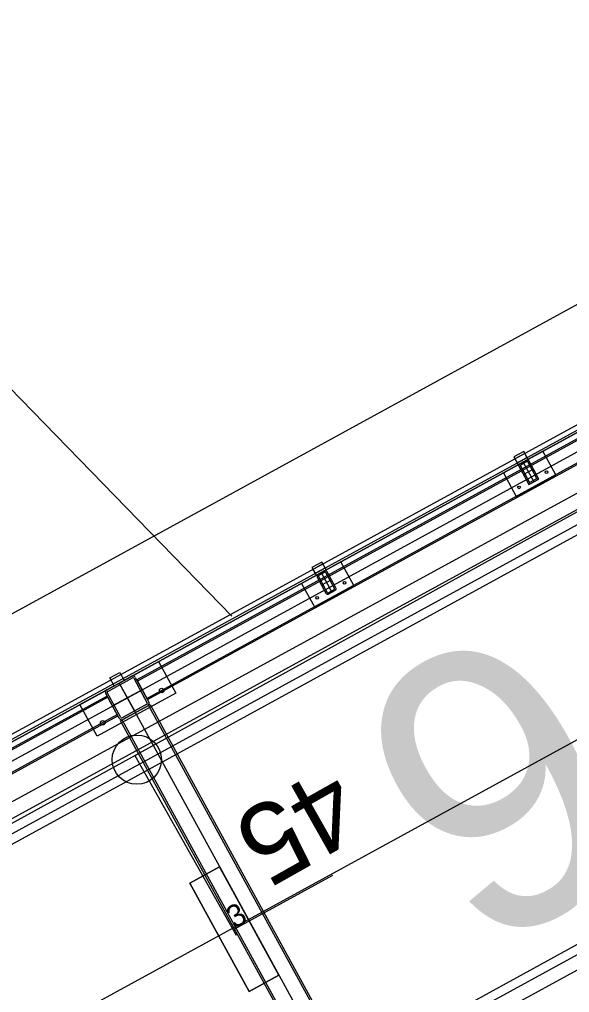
# Model space of a CAD drawing. Extents: x -783978 to -783565, y -1064821 to -1064596.
# Drawn here: x -783781.623 to -783779.173, y -1064690.963 to -1064686.63 of the extents above; entities that cross this region are included whole.
import ezdxf

# ---------------------------------------------------------------- set-up
doc = ezdxf.new("R2010")
doc.units = 0
for name, color, linetype in [('_PS_SO_číslo', 7, 'Continuous'), ('Default', 7, 'Continuous'), ('SO 01_20_01', 7, 'Continuous'), ('SO 01_50_01', 7, 'Continuous'), ('SO 01_74_01', 7, 'Continuous'), ('SO 01_77_01', 7, 'Continuous'), ('SO 01_86_04', 7, 'Continuous')]:
    doc.layers.add(name, color=color, linetype=linetype)

# ---------------------------------------------------------------- blocks, each defined once
blk = doc.blocks.new('POINT_DISPLAY')
at = {"layer": 'Default'}
blk.add_line((0, 0), (0, 0), dxfattribs=at)

msp = doc.modelspace()

# ---------------------------------------------------------------- linework, layer by layer
at = {"layer": '_PS_SO_číslo'}
msp.add_line((-783780.6769, -1064689.2872), (-783798.2896, -1064671.1829), dxfattribs=at)
at = {"layer": 'SO 01_20_01'}
for p, q in [((-783735.0054, -1064663.7532), (-783787.4671, -1064692.4555)), ((-783735.2041, -1064664.4318), (-783786.7885, -1064692.6541)), ((-783786.6445, -1064692.9173), (-783735.3233, -1064664.839)), ((-783738.0171, -1064666.3812), (-783786.4402, -1064692.874)), ((-783786.421, -1064692.9091), (-783737.9979, -1064666.4163)), ((-783737.8741, -1064667.2605), (-783785.3352, -1064693.2269)), ((-783785.6531, -1064694.3127), (-783737.23, -1064667.82)), ((-783737.0912, -1064667.858), (-783785.7805, -1064694.4964)), ((-783737.2108, -1064667.855), (-783785.6339, -1064694.3478))]:
    msp.add_line(p, q, dxfattribs=at)
at = {"layer": 'SO 01_50_01'}
for p, q in [((-783786.7885, -1064692.6541), (-783725.4827, -1064659.1131)), ((-783782.4021, -1064690.2543), (-783778.0156, -1064687.8544)), ((-783782.402, -1064690.2544), (-783778.0156, -1064687.8545)), ((-783782.402, -1064690.2544), (-783778.0156, -1064687.8545))]:
    msp.add_line(p, q, dxfattribs=at)
at = {"layer": 'SO 01_74_01'}
for p, q in [((-783735.2185, -1064664.4055), (-783786.6099, -1064692.5222)), ((-783786.6003, -1064692.5398), (-783735.2089, -1064664.423)), ((-783778.5344, -1064688.1667), (-783781.1005, -1064689.5707)), ((-783778.5314, -1064688.1723), (-783781.0974, -1064689.5762)), ((-783781.0555, -1064689.6529), (-783778.4894, -1064688.2489)), ((-783781.0525, -1064689.6584), (-783778.4864, -1064688.2545)), ((-783779.3771, -1064688.5537), (-783779.421, -1064688.5777)), ((-783779.421, -1064688.5777), (-783779.4018, -1064688.6128)), ((-783779.3723, -1064688.5625), (-783779.4162, -1064688.5865)), ((-783779.4162, -1064688.5865), (-783779.4066, -1064688.604)), ((-783779.4066, -1064688.604), (-783779.3627, -1064688.58)), ((-783779.4018, -1064688.6128), (-783779.3579, -1064688.5888)), ((-783779.3579, -1064688.5888), (-783779.3771, -1064688.5537)), ((-783779.3627, -1064688.58), (-783779.3723, -1064688.5625)), ((-783780.2763, -1064689.0457), (-783780.3202, -1064689.0697)), ((-783780.3202, -1064689.0697), (-783780.301, -1064689.1048)), ((-783780.2715, -1064689.0544), (-783780.3154, -1064689.0784)), ((-783780.2571, -1064689.0808), (-783780.2763, -1064689.0457)), ((-783780.2619, -1064689.072), (-783780.2715, -1064689.0544)), ((-783780.3154, -1064689.0784), (-783780.3058, -1064689.096)), ((-783780.3058, -1064689.096), (-783780.2619, -1064689.072)), ((-783780.301, -1064689.1048), (-783780.2571, -1064689.0808)), ((-783781.2194, -1064689.5616), (-783781.1755, -1064689.5376)), ((-783781.1755, -1064689.5376), (-783781.1563, -1064689.5727)), ((-783781.2002, -1064689.5967), (-783781.2194, -1064689.5616)), ((-783781.1563, -1064689.5727), (-783781.2002, -1064689.5967)), ((-783781.1005, -1064689.5707), (-783781.0525, -1064689.6584)), ((-783781.0974, -1064689.5762), (-783781.0555, -1064689.6529)), ((-783781.232, -1064689.6427), (-783783.7981, -1064691.0466)), ((-783781.229, -1064689.6482), (-783783.7951, -1064691.0521)), ((-783781.1841, -1064689.7304), (-783781.232, -1064689.6427)), ((-783781.1871, -1064689.7249), (-783781.229, -1064689.6482)), ((-783781.1721, -1064689.7523), (-783781.0405, -1064689.6803)), ((-783781.165, -1064689.7485), (-783781.0475, -1064689.6842)), ((-783781.0475, -1064689.6842), (-783780.0395, -1064691.5265)), ((-783781.0405, -1064689.6803), (-783780.0325, -1064691.5226)), ((-783783.7531, -1064691.1288), (-783781.1871, -1064689.7249)), ((-783783.7501, -1064691.1343), (-783781.1841, -1064689.7304)), ((-783780.1641, -1064691.5946), (-783781.1721, -1064689.7523)), ((-783780.1571, -1064691.5908), (-783781.165, -1064689.7485))]:
    msp.add_line(p, q, dxfattribs=at)
for points in [[(-783735.1681, -1064664.4976), (-783787.4762, -1064693.1159)], [(-783779.3662, -1064688.5933), (-783779.3935, -1064688.6082)], [(-783779.3972, -1064688.6211), (-783779.3583, -1064688.6922)], [(-783779.3917, -1064688.618), (-783779.3528, -1064688.6892)], [(-783779.3632, -1064688.5988), (-783779.3904, -1064688.6138)], [(-783779.3798, -1064688.6008), (-783779.3318, -1064688.6885)], [(-783779.3339, -1064688.6326), (-783779.3778, -1064688.6566)], [(-783779.32, -1064688.6712), (-783779.3589, -1064688.6001)], [(-783779.3144, -1064688.6682), (-783779.3534, -1064688.5971)], [(-783779.3485, -1064688.6904), (-783779.3212, -1064688.6755)], [(-783779.3455, -1064688.696), (-783779.3182, -1064688.681)], [(-783780.2964, -1064689.113), (-783780.2575, -1064689.1842)], [(-783780.2654, -1064689.0853), (-783780.2927, -1064689.1002)], [(-783780.2909, -1064689.11), (-783780.252, -1064689.1812)], [(-783780.2624, -1064689.0908), (-783780.2897, -1064689.1057)], [(-783780.279, -1064689.0928), (-783780.231, -1064689.1805)], [(-783780.2192, -1064689.1632), (-783780.2581, -1064689.0921)], [(-783780.2136, -1064689.1602), (-783780.2526, -1064689.089)], [(-783780.2331, -1064689.1246), (-783780.277, -1064689.1486)], [(-783780.2477, -1064689.1824), (-783780.2204, -1064689.1675)], [(-783780.2447, -1064689.1879), (-783780.2174, -1064689.173)], [(-783781.2335, -1064689.615), (-783781.123, -1064689.5545)], [(-783781.2297, -1064689.622), (-783781.1191, -1064689.5615)], [(-783781.1783, -1064689.5847), (-783780.0263, -1064691.6902)], [(-783781.1783, -1064689.5847), (-783781.1063, -1064689.7163)], [(-783781.1137, -1064689.5631), (-783781.0532, -1064689.6736)], [(-783781.1067, -1064689.5593), (-783781.0462, -1064689.6698)], [(-783781.1778, -1064689.7418), (-783781.2383, -1064689.6312)], [(-783781.1708, -1064689.7379), (-783781.2313, -1064689.6274)], [(-783781.0765, -1064689.6145), (-783781.2081, -1064689.6865)], [(-783781.0548, -1064689.6791), (-783781.1654, -1064689.7395)], [(-783781.051, -1064689.6861), (-783781.1615, -1064689.7466)]]:
    msp.add_lwpolyline(points, dxfattribs=at)
for points in [[(-783779.2921, -1064688.5528), (-783779.4675, -1064688.6488), (-783779.41, -1064688.7541), (-783779.2345, -1064688.6581)], [(-783779.3579, -1064688.5888), (-783779.4018, -1064688.6128), (-783779.3538, -1064688.7005), (-783779.3099, -1064688.6765)], [(-783780.1913, -1064689.0448), (-783780.3668, -1064689.1408), (-783780.3092, -1064689.246), (-783780.1337, -1064689.15)], [(-783780.926, -1064689.6291), (-783781.2769, -1064689.8211), (-783781.3537, -1064689.6807), (-783781.0028, -1064689.4887)]]:
    msp.add_lwpolyline(points, close=True, dxfattribs=at)
for centre, radius in [((-783779.2752, -1064688.6461), 0.006), ((-783779.398, -1064688.7133), 0.006), ((-783780.1744, -1064689.1381), 0.006), ((-783780.2972, -1064689.2053), 0.006), ((-783780.9891, -1064689.618), 0.01), ((-783781.2522, -1064689.762), 0.01)]:
    msp.add_circle(centre, radius, dxfattribs=at)
for centre, radius, start, end in [((-783779.3616, -1064688.6016), 0.00945, 28.6835, 118.6835), ((-783779.3889, -1064688.6165), 0.00945, 118.6835, 208.6835), ((-783779.3889, -1064688.6165), 0.00315, 118.6835, 208.6835), ((-783779.3616, -1064688.6016), 0.00315, 28.6835, 118.6835), ((-783779.3227, -1064688.6728), 0.00315, 298.6835, 28.6835), ((-783779.3227, -1064688.6728), 0.00945, 298.6835, 28.6835), ((-783779.35, -1064688.6877), 0.00945, 208.6835, 298.6835), ((-783779.35, -1064688.6877), 0.00315, 208.6835, 298.6835), ((-783780.2881, -1064689.1085), 0.00945, 118.6835, 208.6835), ((-783780.2881, -1064689.1085), 0.00315, 118.6835, 208.6835), ((-783780.2609, -1064689.0936), 0.00945, 28.6835, 118.6835), ((-783780.2609, -1064689.0936), 0.00315, 28.6835, 118.6835), ((-783780.2492, -1064689.1797), 0.00945, 208.6835, 298.6835), ((-783780.2492, -1064689.1797), 0.00315, 208.6835, 298.6835), ((-783780.2219, -1064689.1647), 0.00315, 298.6835, 28.6835), ((-783780.2219, -1064689.1647), 0.00945, 298.6835, 28.6835), ((-783781.1172, -1064689.565), 0.012, 28.6835, 118.6835), ((-783781.1172, -1064689.565), 0.004, 28.6835, 118.6835), ((-783781.2278, -1064689.6255), 0.012, 118.6835, 208.6835), ((-783781.2278, -1064689.6255), 0.004, 118.6835, 208.6835), ((-783781.0567, -1064689.6756), 0.004, 298.6835, 28.6835), ((-783781.0567, -1064689.6756), 0.012, 298.6835, 28.6835), ((-783781.1673, -1064689.736), 0.012, 208.6835, 298.6835), ((-783781.1673, -1064689.736), 0.004, 208.6835, 298.6835)]:
    msp.add_arc(centre, radius, start, end, dxfattribs=at)
at = {"layer": 'SO 01_86_04'}
for p, q in [((-783781.1089, -1064689.9078), (-783780.657, -1064690.7079)), ((-783780.7319, -1064690.4035), (-783780.8635, -1064690.4755)), ((-783780.7319, -1064690.4035), (-783780.8635, -1064690.4755)), ((-783780.8635, -1064690.4755), (-783780.7319, -1064690.4035)), ((-783780.8635, -1064690.4755), (-783780.7319, -1064690.4035)), ((-783780.4679, -1064690.886), (-783780.7319, -1064690.4035)), ((-783780.4679, -1064690.886), (-783780.7319, -1064690.4035)), ((-783780.7319, -1064690.4035), (-783780.4679, -1064690.886)), ((-783780.7319, -1064690.4035), (-783780.4679, -1064690.886)), ((-783780.6657, -1064690.6808), (-783780.227, -1064690.4408)), ((-783780.8635, -1064690.4755), (-783780.5995, -1064690.958)), ((-783780.8635, -1064690.4755), (-783780.5995, -1064690.958)), ((-783780.5995, -1064690.958), (-783780.8635, -1064690.4755)), ((-783780.5995, -1064690.958), (-783780.8635, -1064690.4755)), ((-783780.5995, -1064690.958), (-783780.4679, -1064690.886)), ((-783780.5995, -1064690.958), (-783780.4679, -1064690.886)), ((-783780.4679, -1064690.886), (-783780.5995, -1064690.958)), ((-783780.4679, -1064690.886), (-783780.5995, -1064690.958))]:
    msp.add_line(p, q, dxfattribs=at)
for points in [[(-783738.3222, -1064666.4797), (-783740.5325, -1064667.689), (-783743.1715, -1064669.1328), (-783745.7538, -1064670.5456), (-783748.4385, -1064672.0145), (-783751.0413, -1064673.4385), (-783753.6847, -1064674.8847), (-783756.3281, -1064676.3309), (-783758.9715, -1064677.7772), (-783761.6149, -1064679.2234), (-783764.2583, -1064680.6696), (-783766.9018, -1064682.1159), (-783769.4633, -1064683.5173), (-783772.109, -1064684.9648), (-783774.7882, -1064686.4306), (-783778.1382, -1064688.2722), (-783783.8139, -1064691.3971), (-783785.747, -1064692.4898)], [(-783747.063, -1064670.9765), (-783746.9575, -1064671.1681), (-783786.6893, -1064692.8619), (-783786.185, -1064693.7636)]]:
    msp.add_lwpolyline(points, dxfattribs=at)
msp.add_circle((-783781.1, -1064689.9258), 0.1097, dxfattribs=at)

# ---------------------------------------------------------------- block references
at = {"layer": 'SO 01_86_04', "xscale": 0.010000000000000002, "yscale": 0.009999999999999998, "rotation": 28.683491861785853}
for p in [(-783780.7319, -1064690.4035), (-783780.7319, -1064690.4035), (-783780.8635, -1064690.4755), (-783780.8635, -1064690.4755), (-783780.4679, -1064690.886), (-783780.4679, -1064690.886), (-783780.5995, -1064690.958), (-783780.5995, -1064690.958)]:
    msp.add_blockref('POINT_DISPLAY', p, dxfattribs=at)

# ---------------------------------------------------------------- texts
at = {"layer": 'SO 01_77_01'}
msp.add_text('T6', height=1.25, rotation=208.9107, dxfattribs=at).set_placement((-783778.4945, -1064688.7767))
at = {"layer": 'SO 01_86_04'}
for s, height, rotation, p in [('45', 0.351, 209.46, (-783780.2365, -1064689.9427)), ('3', 0.1, 28.6835, (-783780.6657, -1064690.6808))]:
    msp.add_text(s, height=height, rotation=rotation, dxfattribs=at).set_placement(p)

doc.saveas('drawing.dxf')
